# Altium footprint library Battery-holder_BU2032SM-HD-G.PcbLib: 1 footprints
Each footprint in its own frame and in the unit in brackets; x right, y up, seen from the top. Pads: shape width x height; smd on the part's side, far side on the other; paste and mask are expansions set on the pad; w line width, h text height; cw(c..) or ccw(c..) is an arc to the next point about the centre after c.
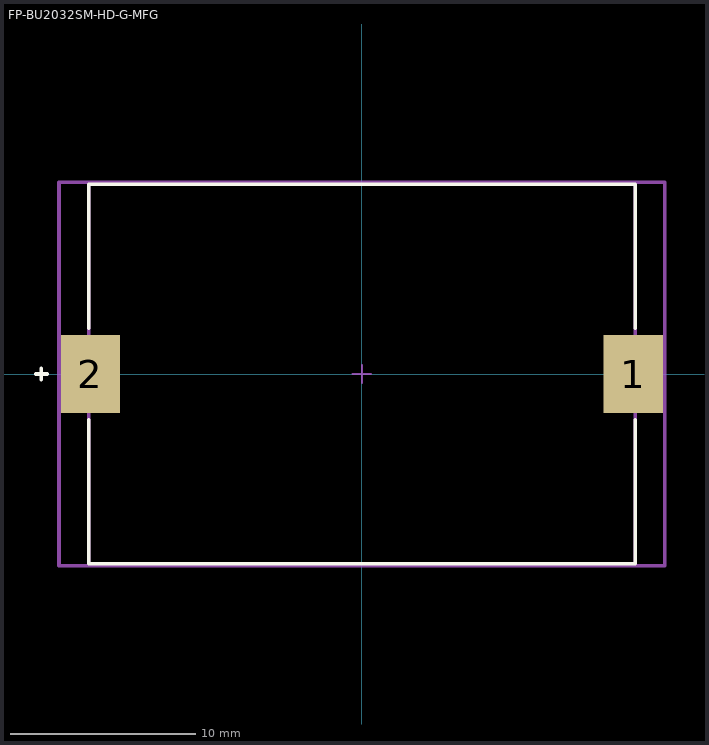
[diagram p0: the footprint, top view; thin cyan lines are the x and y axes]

## FP-BU2032SM-HD-G-MFG [mm]
pads (2):
  rect 3.2x4.2 smd paste+0 mask+0: 1(14.65,0) 2(-14.65,0)
Top Overlay:
  lines w0.2: -17.6,0 -17,0 ; -17.3,-0.3 -17.3,0.3 ; -14.75,-2.475 -14.75,-10.25 14.75,-10.25 14.75,-2.475 ; -14.75,2.475 -14.75,10.25 14.75,10.25 14.75,2.475
Mechanical 5:
  lines w0.2: -16.35,-10.35 16.35,-10.35 16.35,10.35 -16.35,10.35 -16.35,-10.35
  text ".Designator" at 0,-0.001 h1
Mechanical 13:
  lines w0.2: -14.75,-10.25 14.75,-10.25 14.75,10.25 -14.75,10.25 -14.75,-10.25
Mechanical 15:
  lines w0.2: -16.35,-10.35 16.35,-10.35 16.35,10.35 -16.35,10.35 -16.35,-10.35
Mechanical 16:
  lines w0.1: -0.5,0 0.5,0 ; 0,-0.5 0,0.5
3D body "Batt_Memory_Protection_Devices_BU2032SM-HD-G_eec.STEP": height 0.25, standoff 0, extent -16.35,-10.35 16.35,10.35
